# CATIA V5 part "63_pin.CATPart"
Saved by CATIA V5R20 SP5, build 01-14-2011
Part number: 63_pin
Bounding box of the stored display mesh (mm): x -1.988 to 1.988, y 126.362 to 154.362, z 138.262 to 142.238
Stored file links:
  C:\Documents and Settings\anizard\Bureau\13\63_pin.CATPart
  C:\Documents and Settings\anizard\Bureau\13\anizard.CATProduct
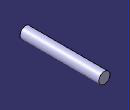
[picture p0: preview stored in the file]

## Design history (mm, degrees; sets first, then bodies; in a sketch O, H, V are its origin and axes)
Set1
  Plane1: linked copy from another document
  Point1: linked copy from another document
  Line1: linked copy from another document
Body1 (main body)
  Sketch1 on Plane1, origin (0, 0, 0), H (0, 1, 0), V (0, 0, 1)
    line L1 (126.3619, 142.25) -> (154.3619, 142.25)
    line L2 (154.3619, 142.25) -> (154.3619, 140.25)
    line L3 (154.3619, 140.25) -> (126.3619, 140.25)
    line L4 (126.3619, 140.25) -> (126.3619, 142.25)
    reference projected point E1 (140.3619, 140.25) from Point1
    reference projected line E2 (140.3619, -190) -> (140.3619, 190) from Line1
    axis line L5 (179.0647, 140.25) -> (110.9363, 140.25)
    reference projected point E3 (140.3619, 140.25) from Point1
    distance L3 L1 = 2
    distance L2 L4 = 28
    horizontal: L1 H, L3 H, L5 H
    vertical: L2 V, L4 V
    coincidence: L3 E1, L5 E3
    symmetry: L2 L4 E2
  Shaft1: profile Sketch1, axis Sketch1.L5, angle 360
